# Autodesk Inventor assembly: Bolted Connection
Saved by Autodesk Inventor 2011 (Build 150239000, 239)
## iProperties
Created: 2020-12
Part Number: Bolted Connection
Document SubType Name: Assembly
Designer: PC
ClientObjectVersion: 1
Author: PC
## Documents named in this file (3)
- C:\Users\PC\Documents\Inventor\workshop-crane-powered-by-drill\estructura-principal\Design Accelerator\Bolted Connection1.iam
- C:\Users\PC\Documents\Inventor\Content Center Files\R2011\en-US\DIN 931-1\DIN 931-1 - M14 x 90.ipt
- C:\Users\PC\Documents\Inventor\Content Center Files\R2011\en-US\DIN 555\DIN 555-5 - M14.ipt
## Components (2 placed, 2 different names)
1. DIN 931-1 - replaced by DIN EN 24014 M14 x 90:1
2. DIN 555 - replaced by DIN EN 24034 M14:1
